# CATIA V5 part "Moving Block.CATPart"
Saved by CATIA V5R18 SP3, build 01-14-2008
Part number: Air Cylinder Fix Part
Bounding box of the stored display mesh (mm): x -38.5 to 38.5, y -37.5 to 37.5, z 0 to 68
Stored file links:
  E:\#00 CATIA V5 Movie\#03 CATIA V5 Data\#07 KIN\Balance Unit (1)\Moving Block.CATPart
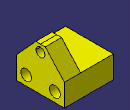
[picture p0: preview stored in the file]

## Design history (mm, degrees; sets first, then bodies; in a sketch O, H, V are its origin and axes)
Body1 (main body)
  Sketch1 on yz-plane, origin (0, 0, 0), H (0, 1, 0), V (0, 0, 1)
    point P1 (0, 68)
    line L1 (0, 68) -> (7.5, 68)
    point P2 (7.5, 68)
    line L2 (7.5, 68) -> (37.5, 35)
    point P3 (37.5, 35)
    line L3 (37.5, 35) -> (37.5, 0)
    point P4 (37.5, 0)
    line L4 (37.5, 0) -> (0, 0)
    point P5 (-7.5, 68)
    point P6 (-37.5, 35)
    point P7 (-37.5, 0)
    line L5 (-7.5, 68) -> (-37.5, 35)
    line L6 (-37.5, 35) -> (-37.5, 0)
    point P8 (0, 0)
    line L7 (-37.5, 0) -> (0, 0)
    point P9 (0, 68)
    line L8 (0, 68) -> (-7.5, 68)
    circle A1 centre (0, 57) radius 7
    point P10 (0, 57)
    length L1 = 7.5
    radius A1 = 7
    distance P10 L4 = 57
    distance L1 L4 = 68
    length L3 = 35
    length L4 = 37.5
    coincidence: P1 V, P4 H, P10 V, O P8, P1 P9
    horizontal: L1 H, L4 H
    vertical: L3 V
    symmetry: P2 P5 V, P3 P6 V, P4 P7 V, L2 L5 V, L3 L6 V, O P8 V, L4 L7 V, P1 P9 V, L1 L8 V
  Pad1: profile Sketch1, direction (1, 0, 0), length 38.5, mirrored extent
  Sketch2 on zx-plane, origin (0, 0, 0), H (-1, 0, 0), V (0, 0, 1)
    line L1 (-13, 68) -> (38.5, 68)
    line L2 (38.5, 68) -> (38.5, 35)
    line L3 (38.5, 35) -> (-13, 35)
    line L4 (-13, 35) -> (-13, 68)
    reference intersected line E1 through (38.5, 0) direction (0, -1) from start face of Pad1
    reference intersected line E2 (-38.5, 68) -> (38.5, 68) from face of Pad1 from Sketch1.L1
    distance L4 L2 = 51.5
    distance L3 H = 35
    horizontal: L1 H, L3 H
    vertical: L2 V, L4 V
    coincidence: L2 E1, L1 E2
  Pocket1: profile Sketch2, direction (0, -1, 0), length 39.25, mirrored extent
  Sketch3 on end face of Pad1, origin (38.5, 22.5, 15), H (0, 1, 0), V (0, 0, 1)
    point P1 (0, 0)
    reference projected point E1 (0, 0) from Sketch4.P1
    coincidence: E1 P1
  Hole1: placed by Sketch3, at (38.5, 22.5, 15) direction (-1, 0, 0), diameter 11, through (limit type 6), counterbore diameter 17, counterbore depth 20
  Sketch4 on end face of Pad1, origin (38.5, 0, 0), H (0, 1, 0), V (0, 0, 1)
    point P1 (22.5, 15)
    point P2 (-22.5, 15)
    distance P1 H = 15
    distance P1 P2 = 45
    symmetry: P1 P2 V
  UserPattern1: of Hole1, copies 2, at the points of Sketch4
